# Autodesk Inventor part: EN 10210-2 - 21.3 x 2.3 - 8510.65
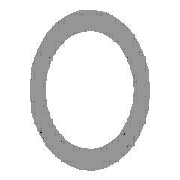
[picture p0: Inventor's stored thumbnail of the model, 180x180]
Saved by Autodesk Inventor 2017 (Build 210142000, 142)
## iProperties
Created: 2017-11
Part Number: EN 10210-2 - 21.3 x 2.3 - 8510.65
Material: Steel, Mild
Description: Pipe
Document SubType Name: Modeling
Standard: DIN
Designer: iusti
Standard Revision: 2006-07
Standards Organization: DIN
Language: en-US
Size Designation: 21.3 x 2.3
Categories: <MemberInstance><Categories><Category DisplayName="Structural Shapes" InternalName="089c4875-fa83-4c05-b084-43b9cc11f5ed" Mnemonic="GRDR"><CategoryParameter Dis
Stock Number: 21.3 x 2.3
Density: 7.85 g/cm^3
Appearance: Semi-Polished
_CCFamilyMember: 1
_CCFamilyDisplayName: DIN EN 10210-2 - Pipe
_FrameMemberDoc: Frame Member File
_Version: 15.0.0
_GetPNFromCC: 1
IsCustomPart: 1
Author: iusti
G_L: 8510.650 mm
G_W: 21.300 mm
G_H: 21.300 mm
+AA30E1D5-0686-4E1F-BB21-01C88EDD7D39+CUTDETAIL1: Miter 45.00 deg
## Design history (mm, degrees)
node "Start plane"
node "End plane"
sketch "Sketch"
  geometry: C1 r 8.35 at (0, 0); C2 r 10.65 at (0, 0); 2 further points
  constraints: 3 coincident, 2 centre point
  dimensions: "d0" = 21.3 diameter of C2 (= G_H); "d1" = 2.3 radial gap between concentric circles of C2 C1 (= G_T)
extrude "Body" new body sketch "Sketch" stored distance "d2" = 8510.65 (= G_L); taper "d3" = 0 deg
node "Driven Length"
  sketch "Sketch3"
    geometry: L1 (0, 0)-(10, 0) reference
    constraints: 2 end point, 1 horizontal
  workplane "Work Plane3"
  sketch "Sketch4"
    geometry: L1 (-2, 0)-(12, 0) reference; L2 (-2, 8510.65)-(12, 8510.65) reference
    dimensions: "d7" = 8510.65 distance between parallel lines of L1 L2 (derived)
workplane "Work Plane4"
split "Split1"
body "Solid1"
other parameters: "G_H" = 21.3 [user parameter; used in 1 equation term], "G_T" = 2.3 [user parameter; used in 1 equation term], "G_L" = 8510.65 (= d7) [user parameter; used in 1 equation term], "G_OFFSET_START" = 0 [user parameter; used in 1 equation term], "G_OFFSET_END" = -493.17913 [user parameter; used in 1 equation term], "d4" = 0 (computed from G_OFFSET_START), "d5" = 8510.65 (= G_OFFSET_END + B_L), "B_L" = 9003.82913 [user parameter; used in 1 equation term], "d6" = 90 deg
